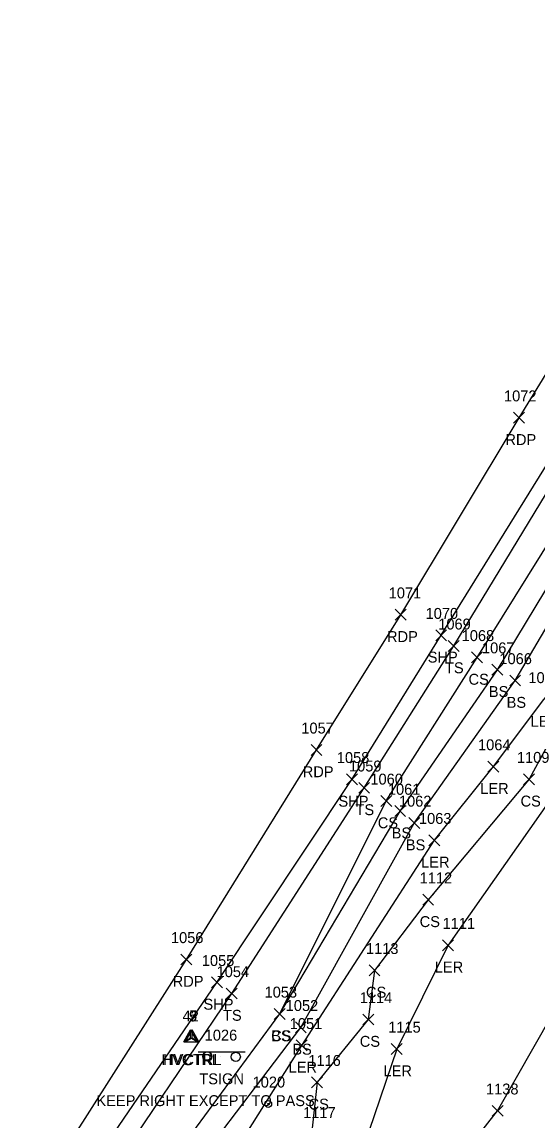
# Model space of a CAD drawing. Extents: x 1483143 to 1488182, y 802902 to 807581.
# Drawn here: x 1487094.3 to 1487188.6, y 804993.1 to 805194.3 of the extents above; entities that cross this region are included whole.
import ezdxf

# ---------------------------------------------------------------- set-up
doc = ezdxf.new("R2010")
doc.units = 0
for name, color, linetype in [('C_A', 7, 'Continuous'), ('C_I', 7, 'Continuous'), ('CBP', 7, 'Continuous'), ('CPSM', 7, 'Continuous'), ('L_A', 7, 'Continuous'), ('L_I', 7, 'Continuous'), ('L_TIC', 7, 'Continuous'), ('LARO', 7, 'Continuous'), ('LAWA', 7, 'Continuous'), ('LELB', 7, 'Continuous'), ('P_A', 7, 'Continuous'), ('P_I', 7, 'Continuous'), ('P_TIC', 7, 'Continuous'), ('PET', 7, 'Continuous'), ('PSP', 7, 'Continuous'), ('S_A', 7, 'Continuous'), ('S_C', 7, 'Continuous'), ('S_I', 7, 'Continuous'), ('SSGN', 7, 'Continuous')]:
    doc.layers.add(name, color=color, linetype=linetype)

msp = doc.modelspace()

# ---------------------------------------------------------------- linework, layer by layer
at = {"layer": 'CBP'}
for radius in [0.625, 0.0833]:
    msp.add_circle((1487139.35, 804996.09), radius, dxfattribs=at)
at = {"layer": 'CPSM'}
for p, q in [((1487123.88, 805007.48), (1487125.13, 805009.64)), ((1487123.88, 805007.48), (1487125.13, 805008.2)), ((1487124.16, 805007.49), (1487125.41, 805009.66)), ((1487124.16, 805007.48), (1487125.41, 805009.65)), ((1487124.16, 805007.49), (1487125.41, 805008.21)), ((1487124.16, 805007.48), (1487125.41, 805008.2)), ((1487126.38, 805007.48), (1487125.13, 805009.64)), ((1487125.13, 805008.2), (1487125.13, 805009.64)), ((1487125.13, 805008.2), (1487125.13, 805008.2)), ((1487125.13, 805008.2), (1487126.38, 805007.48)), ((1487126.66, 805007.49), (1487125.41, 805009.66)), ((1487125.41, 805008.21), (1487125.41, 805009.66)), ((1487126.66, 805007.48), (1487125.41, 805009.65)), ((1487125.41, 805008.2), (1487125.41, 805009.65)), ((1487125.41, 805008.21), (1487125.41, 805008.21)), ((1487125.41, 805008.21), (1487126.66, 805007.49)), ((1487125.41, 805008.2), (1487125.41, 805008.2)), ((1487125.41, 805008.2), (1487126.66, 805007.48)), ((1487123.88, 805007.48), (1487126.38, 805007.48)), ((1487124.16, 805007.49), (1487126.66, 805007.49)), ((1487124.16, 805007.48), (1487126.66, 805007.48))]:
    msp.add_line(p, q, dxfattribs=at)
at = {"layer": 'L_TIC'}
for points in [[(1487172.31, 805078.98), (1487174.31, 805080.98)], [(1487174.31, 805078.98), (1487172.31, 805080.98)], [(1487176.59, 805076.87), (1487178.59, 805078.87)], [(1487178.59, 805076.87), (1487176.59, 805078.87)], [(1487180.31, 805074.62), (1487182.31, 805076.62)], [(1487182.31, 805074.62), (1487180.31, 805076.62)], [(1487183.56, 805072.64), (1487185.56, 805074.64)], [(1487185.56, 805072.64), (1487183.56, 805074.64)], [(1487179.59, 805056.87), (1487181.59, 805058.87)], [(1487181.59, 805056.87), (1487179.59, 805058.87)], [(1487186.1, 805054.56), (1487188.1, 805056.56)], [(1487188.1, 805054.56), (1487186.1, 805056.56)], [(1487155.92, 805052.98), (1487157.92, 805054.98)], [(1487157.92, 805052.98), (1487155.92, 805054.98)], [(1487159.97, 805050.58), (1487161.97, 805052.58)], [(1487161.97, 805050.58), (1487159.97, 805052.58)], [(1487162.51, 805048.72), (1487164.51, 805050.72)], [(1487164.51, 805048.72), (1487162.51, 805050.72)], [(1487165.09, 805046.54), (1487167.09, 805048.54)], [(1487167.09, 805046.54), (1487165.09, 805048.54)], [(1487168.77, 805043.38), (1487170.77, 805045.38)], [(1487170.77, 805043.38), (1487168.77, 805045.38)], [(1487167.64, 805032.48), (1487169.64, 805034.48)], [(1487169.64, 805032.48), (1487167.64, 805034.48)], [(1487171.27, 805024.16), (1487173.27, 805026.16)], [(1487173.27, 805024.16), (1487171.27, 805026.16)], [(1487157.81, 805019.55), (1487159.81, 805021.55)], [(1487159.81, 805019.55), (1487157.81, 805021.55)], [(1487131.66, 805015.32), (1487133.66, 805017.32)], [(1487133.66, 805015.32), (1487131.66, 805017.32)], [(1487140.45, 805011.57), (1487142.45, 805013.57)], [(1487142.45, 805011.57), (1487140.45, 805013.57)], [(1487140.45, 805011.57), (1487142.45, 805013.57)], [(1487142.45, 805011.57), (1487140.45, 805013.57)], [(1487156.67, 805010.55), (1487158.67, 805012.55)], [(1487158.67, 805010.55), (1487156.67, 805012.55)], [(1487144.32, 805009.11), (1487146.32, 805011.11)], [(1487146.32, 805009.11), (1487144.32, 805011.11)], [(1487144.49, 805005.81), (1487146.49, 805007.81)], [(1487146.49, 805005.81), (1487144.49, 805007.81)], [(1487161.87, 805005.15), (1487163.87, 805007.15)], [(1487163.87, 805005.15), (1487161.87, 805007.15)], [(1487147.3, 804999.05), (1487149.3, 805001.05)], [(1487149.3, 804999.05), (1487147.3, 805001.05)], [(1487180.36, 804993.82), (1487182.36, 804995.82)], [(1487182.36, 804993.82), (1487180.36, 804995.82)]]:
    msp.add_lwpolyline(points, dxfattribs=at)
at = {"layer": 'LARO'}
for points in [[(1487124.31, 804973.13), (1487145.49, 805006.81), (1487169.77, 805044.38), (1487180.59, 805057.87), (1487189.8, 805070.17), (1487199.3, 805080.96), (1487217.89, 805101.74), (1487229.45, 805124.32), (1487246.83, 805150.76), (1487254.41, 805169.19), (1487269.28, 805204.96), (1487282.34, 805212.7), (1487284.63, 805226.5), (1487290.62, 805235.83), (1487297.31, 805243.76), (1487306.73, 805267.09), (1487309.81, 805276.71), (1487327.69, 805305.4), (1487333.49, 805320.05), (1487351.27, 805341.81), (1487376.58, 805390.13), (1487400.9, 805431.24), (1487423.77, 805476.17), (1487448.72, 805522.61)], [(1487224.88, 805102.18), (1487218.96, 805092.75), (1487207.16, 805077.22), (1487197.72, 805064.88), (1487191.27, 805052.19), (1487172.27, 805025.16), (1487162.87, 805006.15), (1487154.72, 804982.09), (1487145.82, 804977.85), (1487136.39, 804963.75), (1487123.38, 804946.04), (1487114.55, 804933.59), (1487107.15, 804926.23), (1487097.47, 804917.18), (1487108.5, 804913.17)]]:
    msp.add_lwpolyline(points, dxfattribs=at)
at = {"layer": 'LAWA'}
msp.add_lwpolyline([(1487164.31, 804973.06), (1487181.36, 804994.82), (1487194.73, 805018.42), (1487204.56, 805038.94), (1487212.1, 805055.28), (1487210.34, 805064.51), (1487218.24, 805082.58), (1487225.12, 805089.2), (1487235.87, 805102.93), (1487242.66, 805101.92), (1487244.56, 805101.79), (1487253.92, 805111.46), (1487254.69, 805139.81), (1487264.81, 805134.72), (1487277.92, 805155.83), (1487279.64, 805173.04), (1487288.55, 805192.53), (1487294.52, 805206.51)], dxfattribs=at)
at = {"layer": 'LELB'}
for points in [[(1487108.71, 804980.78), (1487132.66, 805016.32), (1487156.92, 805053.98), (1487173.31, 805079.98), (1487194.46, 805114.79), (1487207.05, 805135.95), (1487220.86, 805159.73), (1487233.38, 805181.3), (1487254.33, 805216.27), (1487271.44, 805245.69), (1487289.79, 805275.85), (1487308.89, 805309.94), (1487335.6, 805356.15), (1487359.27, 805398.59), (1487383.94, 805443.57), (1487406.66, 805485.41), (1487431.45, 805531.24)], [(1487141.45, 805012.57), (1487160.97, 805051.58), (1487177.59, 805077.87), (1487198.8, 805111.86), (1487211.59, 805133.5), (1487225.91, 805156.73), (1487238.62, 805176.26), (1487258.28, 805214.16), (1487275.11, 805243.36), (1487293.13, 805273.9), (1487313.26, 805307.35), (1487339.04, 805353.08), (1487362.83, 805397.01), (1487388.55, 805442.86), (1487410.04, 805483.24), (1487436.07, 805529.53)], [(1487115.55, 804977.3), (1487141.45, 805012.57), (1487163.51, 805049.72), (1487181.31, 805075.62), (1487202.21, 805110.17), (1487217.83, 805130.45), (1487232, 805156.36), (1487242.54, 805175.79), (1487260.94, 805211.88), (1487278.65, 805241.13), (1487296.94, 805270.92), (1487316.03, 805304.83), (1487341.87, 805350.7), (1487367.6, 805395.34), (1487392.63, 805437.94), (1487413.83, 805481.53), (1487440.22, 805526.89)], [(1487119.27, 804975.75), (1487145.32, 805010.11), (1487166.09, 805047.54), (1487184.56, 805073.64), (1487204.9, 805108.12), (1487221.47, 805128.3), (1487235.08, 805155.22), (1487247.48, 805170.55), (1487262.97, 805210.14), (1487282.96, 805240.11), (1487299.52, 805269.42), (1487319.05, 805303.47), (1487344.42, 805349.03), (1487372.12, 805390.86), (1487397.58, 805436.46), (1487417, 805480.8), (1487442.28, 805525.8)], [(1487246.83, 805150.76), (1487242.89, 805139.86), (1487233.12, 805123.13), (1487224.88, 805102.18), (1487217.52, 805094.61), (1487202.79, 805080.03), (1487193.63, 805067.59), (1487187.1, 805055.56), (1487168.64, 805033.48), (1487158.81, 805020.55), (1487157.67, 805011.55), (1487148.3, 805000.05), (1487147.3, 804990.5), (1487140.47, 804987.56), (1487138.01, 804979.27), (1487134.54, 804971.88), (1487127.64, 804963.81), (1487118.59, 804952.09), (1487110, 804937.1), (1487101.9, 804929.94), (1487094.26, 804919.39), (1487097.47, 804917.18)]]:
    msp.add_lwpolyline(points, dxfattribs=at)
at = {"layer": 'P_TIC'}
for points in [[(1487184.29, 805120.77), (1487186.29, 805122.77)], [(1487186.29, 805120.77), (1487184.29, 805122.77)], [(1487162.62, 805084.69), (1487164.62, 805086.69)], [(1487164.62, 805084.69), (1487162.62, 805086.69)], [(1487170.02, 805080.93), (1487172.02, 805082.93)], [(1487172.02, 805080.93), (1487170.02, 805082.93)], [(1487147.19, 805059.93), (1487149.19, 805061.93)], [(1487149.19, 805059.93), (1487147.19, 805061.93)], [(1487153.68, 805054.53), (1487155.68, 805056.53)], [(1487155.68, 805054.53), (1487153.68, 805056.53)], [(1487123.37, 805021.55), (1487125.37, 805023.55)], [(1487125.37, 805021.55), (1487123.37, 805023.55)], [(1487128.96, 805017.35), (1487130.96, 805019.35)], [(1487130.96, 805017.35), (1487128.96, 805019.35)]]:
    msp.add_lwpolyline(points, dxfattribs=at)
at = {"layer": 'PET'}
msp.add_lwpolyline([(1487100.01, 804984.32), (1487124.37, 805022.55), (1487148.19, 805060.93), (1487163.62, 805085.69), (1487185.29, 805121.77), (1487197.78, 805142.12), (1487211.62, 805165.78), (1487224.01, 805186.83), (1487244.77, 805222.1), (1487262.9, 805253.28), (1487279.63, 805281.48), (1487299.46, 805315.66), (1487325.71, 805361.73), (1487348.03, 805401.83), (1487373.61, 805448.47), (1487396.33, 805490.41), (1487421.9, 805537.94)], dxfattribs=at)
at = {"layer": 'PSP'}
msp.add_lwpolyline([(1487105.23, 804982.13), (1487129.96, 805018.35), (1487154.68, 805055.53), (1487171.02, 805081.93), (1487192.51, 805116.63), (1487204.72, 805136.95), (1487219.03, 805160.88), (1487231.84, 805182.51), (1487252.47, 805217.19), (1487269.89, 805246.6), (1487288.3, 805277.02), (1487307.74, 805310.87), (1487334.08, 805357.49), (1487356.35, 805397.12), (1487382.38, 805444.5), (1487405.03, 805486.21), (1487429.8, 805532.42)], dxfattribs=at)
at = {"layer": 'SSGN'}
for p, q in [((1487126.53, 805005.61), (1487135.13, 805005.61)), ((1487130.56, 805004.71), (1487130.56, 805004.71))]:
    msp.add_line(p, q, dxfattribs=at)
for centre in [(1487128.19, 805004.78), (1487133.41, 805004.71)]:
    msp.add_circle(centre, 0.833, dxfattribs=at)

# ---------------------------------------------------------------- texts
at = {"layer": 'C_A'}
for p in [(1487119.82, 805003.2), (1487120.1, 805003.2), (1487120.11, 805003.21)]:
    msp.add_text('HVCTRL', height=2, dxfattribs=at).set_placement(p)
at = {"layer": 'C_I'}
for s, p in [('42', (1487123.67, 805011.2)), ('5', (1487124.85, 805011.21)), ('9', (1487124.84, 805011.2)), ('1020', (1487136.49, 804999.09))]:
    msp.add_text(s, height=2, dxfattribs=at).set_placement(p)
at = {"layer": 'L_A'}
for s, p in [('TS', (1487171.72, 805074.98)), ('CS', (1487176.03, 805072.87)), ('BS', (1487179.75, 805070.62)), ('BS', (1487183, 805068.64)), ('LER', (1487187.39, 805065.17)), ('LER', (1487178.17, 805052.87)), ('CS', (1487185.55, 805050.56)), ('TS', (1487155.33, 805048.98)), ('CS', (1487159.41, 805046.58)), ('BS', (1487161.95, 805044.72)), ('BS', (1487164.54, 805042.54)), ('LER', (1487167.35, 805039.38)), ('CS', (1487167.08, 805028.48)), ('LER', (1487169.85, 805020.16)), ('CS', (1487157.25, 805015.55)), ('TS', (1487131.07, 805011.32)), ('CS', (1487139.89, 805007.57)), ('BS', (1487139.89, 805007.57)), ('CS', (1487156.11, 805006.55)), ('BS', (1487143.76, 805005.11)), ('LER', (1487143.08, 805001.81)), ('LER', (1487160.46, 805001.15)), ('CS', (1487146.74, 804995.05))]:
    msp.add_text(s, height=2, dxfattribs=at).set_placement(p)
at = {"layer": 'L_I'}
for s, p in [('1069', (1487170.48, 805082.98)), ('1068', (1487174.77, 805080.87)), ('1067', (1487178.49, 805078.62)), ('1066', (1487181.68, 805076.64)), ('1065', (1487186.99, 805073.17)), ('1064', (1487177.77, 805060.87)), ('1109', (1487184.89, 805058.56)), ('1059', (1487154.14, 805056.98)), ('1060', (1487158.06, 805054.58)), ('1061', (1487161.26, 805052.72)), ('1062', (1487163.28, 805050.54)), ('1063', (1487166.95, 805047.38)), ('1112', (1487167.08, 805036.48)), ('1111', (1487171.27, 805028.16)), ('1113', (1487157.25, 805023.55)), ('1054', (1487129.89, 805019.32)), ('1053', (1487138.68, 805015.57)), ('1053', (1487138.68, 805015.57)), ('1114', (1487156.11, 805014.55)), ('1052', (1487142.55, 805013.11)), ('1051', (1487143.29, 805009.81)), ('1115', (1487161.32, 805009.15)), ('1116', (1487146.69, 805003.05)), ('1138', (1487179.23, 804997.82)), ('1117', (1487145.74, 804993.5))]:
    msp.add_text(s, height=2, dxfattribs=at).set_placement(p)
at = {"layer": 'P_A'}
for s, p in [('RDP', (1487182.78, 805116.77)), ('RDP', (1487161.1, 805080.69)), ('SHP', (1487168.55, 805076.93)), ('RDP', (1487145.67, 805055.93)), ('SHP', (1487152.21, 805050.53)), ('RDP', (1487121.86, 805017.55)), ('SHP', (1487127.49, 805013.35))]:
    msp.add_text(s, height=2, dxfattribs=at).set_placement(p)
at = {"layer": 'P_I'}
for s, p in [('1072', (1487182.52, 805124.77)), ('1071', (1487161.41, 805088.69)), ('1070', (1487168.16, 805084.93)), ('1057', (1487145.41, 805063.93)), ('1058', (1487151.91, 805058.53)), ('1056', (1487121.54, 805025.55)), ('1055', (1487127.19, 805021.35))]:
    msp.add_text(s, height=2, dxfattribs=at).set_placement(p)
at = {"layer": 'S_A'}
msp.add_text('TSIGN', height=2, dxfattribs=at).set_placement((1487126.73, 804999.69))
at = {"layer": 'S_C'}
msp.add_text('KEEP RIGHT EXCEPT TO PASS', height=2, dxfattribs=at).set_placement((1487107.89, 804995.69))
at = {"layer": 'S_I'}
msp.add_text('1026', height=2, dxfattribs=at).set_placement((1487127.72, 805007.69))

doc.saveas('drawing.dxf')
